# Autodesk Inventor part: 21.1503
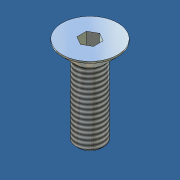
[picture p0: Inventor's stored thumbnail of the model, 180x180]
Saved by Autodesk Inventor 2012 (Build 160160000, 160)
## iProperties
Created: 2006-12
Part Number: 21.1503
Material: Steel, Mild
Description: M5x16 C'SUNK
Document SubType Name: Modeling
Standard: DIN 7991
Designer: Andy Moles
Standards Organization: DIN
Language: en-US
Size Designation: M5x16
Categories: <MemberInstance Version="R10.0.0"><Categories><Category DisplayName="Fasteners" InternalName="e4da775c-781d-43d5-af7c-5136215cf5a6" Mnemonic="FSTN"><Category Di
Density: 7.86 g/cm^3
Mass: 2.97248 g
Surface Area: 4.18131 cm^2
Volume: 0.378178 cm^3
Vendor: S
Author: Andy Moles
Revision Number: 1
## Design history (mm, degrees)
node "Sketch1"
node "WorkPoint1"
sketch "Sketch2"
  geometry: L1 (-2.5, -16)-(0, -16); L2 (-2.5, -2.8)-(-2.5, -16); L3 (-5, -0.3)-(-2.5, -2.8); L4 (-5, 0)-(-5, -0.3); L5 (0, 0)-(-5, 0); L6 (0, -16)-(0, 0); L7 (0, -16)-(0, 0); L8 (0, -17.6)-(0, 4.8) reference; L9 (0.5, 0)-(-6.5, 0) reference
  constraints: 14 end point, 3 vertical, 2 horizontal
  dimensions: "d1" = 45 deg angle of L3 L6; "d3" = 5 distance of L5.start L4.start (= 0.5 x dk); "d5" = 2.5 distance of L1.start L1.end (= 0.5 x NND); "d7" = 16 distance of L1.end L5.start (= NLG); "ParC" = 0.3 distance of L4.start L3.start; "d22" = 0 distance between parallel lines of L8 L6; "d23" = 0 distance between parallel lines of L9 L5
fillet "Fillet1" dims "d18" = 0.2 (= r)
chamfer "Chamfer1" distance "d19" = 0.4 (= 0.5 x PTC); stored, may be unused: angle "d20" = 45 deg, second distance "d39" = 0.4 (= 0.5 x PTC)
node "MSC_A1"
node "MSC_PF1"
node "MSC_PT1"
body "Solid1"
revolve "Revolution1" stored, may be unused: angle "d8" = 360 deg
sketch "Sketch3"
  geometry: L1 (-1.5, 0.866)-(-1.5, -0.866); L2 (0, 1.732)-(-1.5, 0.866); L3 (1.5, 0.866)-(0, 1.732); L4 (1.5, -0.866)-(1.5, 0.866); L5 (0, -1.732)-(1.5, -0.866); L6 (-1.5, -0.866)-(0, -1.732); C1 r 1.5 at (0, 0); C2 r 2.5 at (0, 0) reference
  constraints: 12 end point, 6 tangent, 2 parallel, 2 vertical, 1 centre point, 1 concentric
  dimensions: "d11" = 3 diameter of C1 (= ParS); "d13" = 120 deg angle of L1 L2; "d15" = 120 deg angle of L6 L1
extrude "Extrusion1" cut sketch "Sketch3" distance "d16" = 2.3 (= ParT); taper "d17" = 0 deg
thread "Thread1" dims "d35" = 0, "b" = 13.5
other parameters: "NND" = 5 [user parameter; used in 2 equation terms], "PTC" = 0.8 [user parameter; used in 2 equation terms], "ParK" = 2.8 [user parameter], "ParS" = 3 [user parameter; used in 1 equation term], "ParT" = 2.3 [user parameter; used in 1 equation term], "r" = 0.2 [user parameter; used in 1 equation term], "NLG" = 16 [user parameter; used in 1 equation term], "d0" = 45 deg (derived), "d2" = 3 (derived), "d4" = 1.5 (derived), "d6" = 8 (derived), "d9" = 0, "d10" = 2 (derived), "d12" = 120 deg (derived), "d14" = 120 deg (derived), "d37" = 0, "d38" = 0, "d40" = 0, "d41" = 0, "d42" = 0, "THREADDIA" = 5 (= NND) [user parameter]
